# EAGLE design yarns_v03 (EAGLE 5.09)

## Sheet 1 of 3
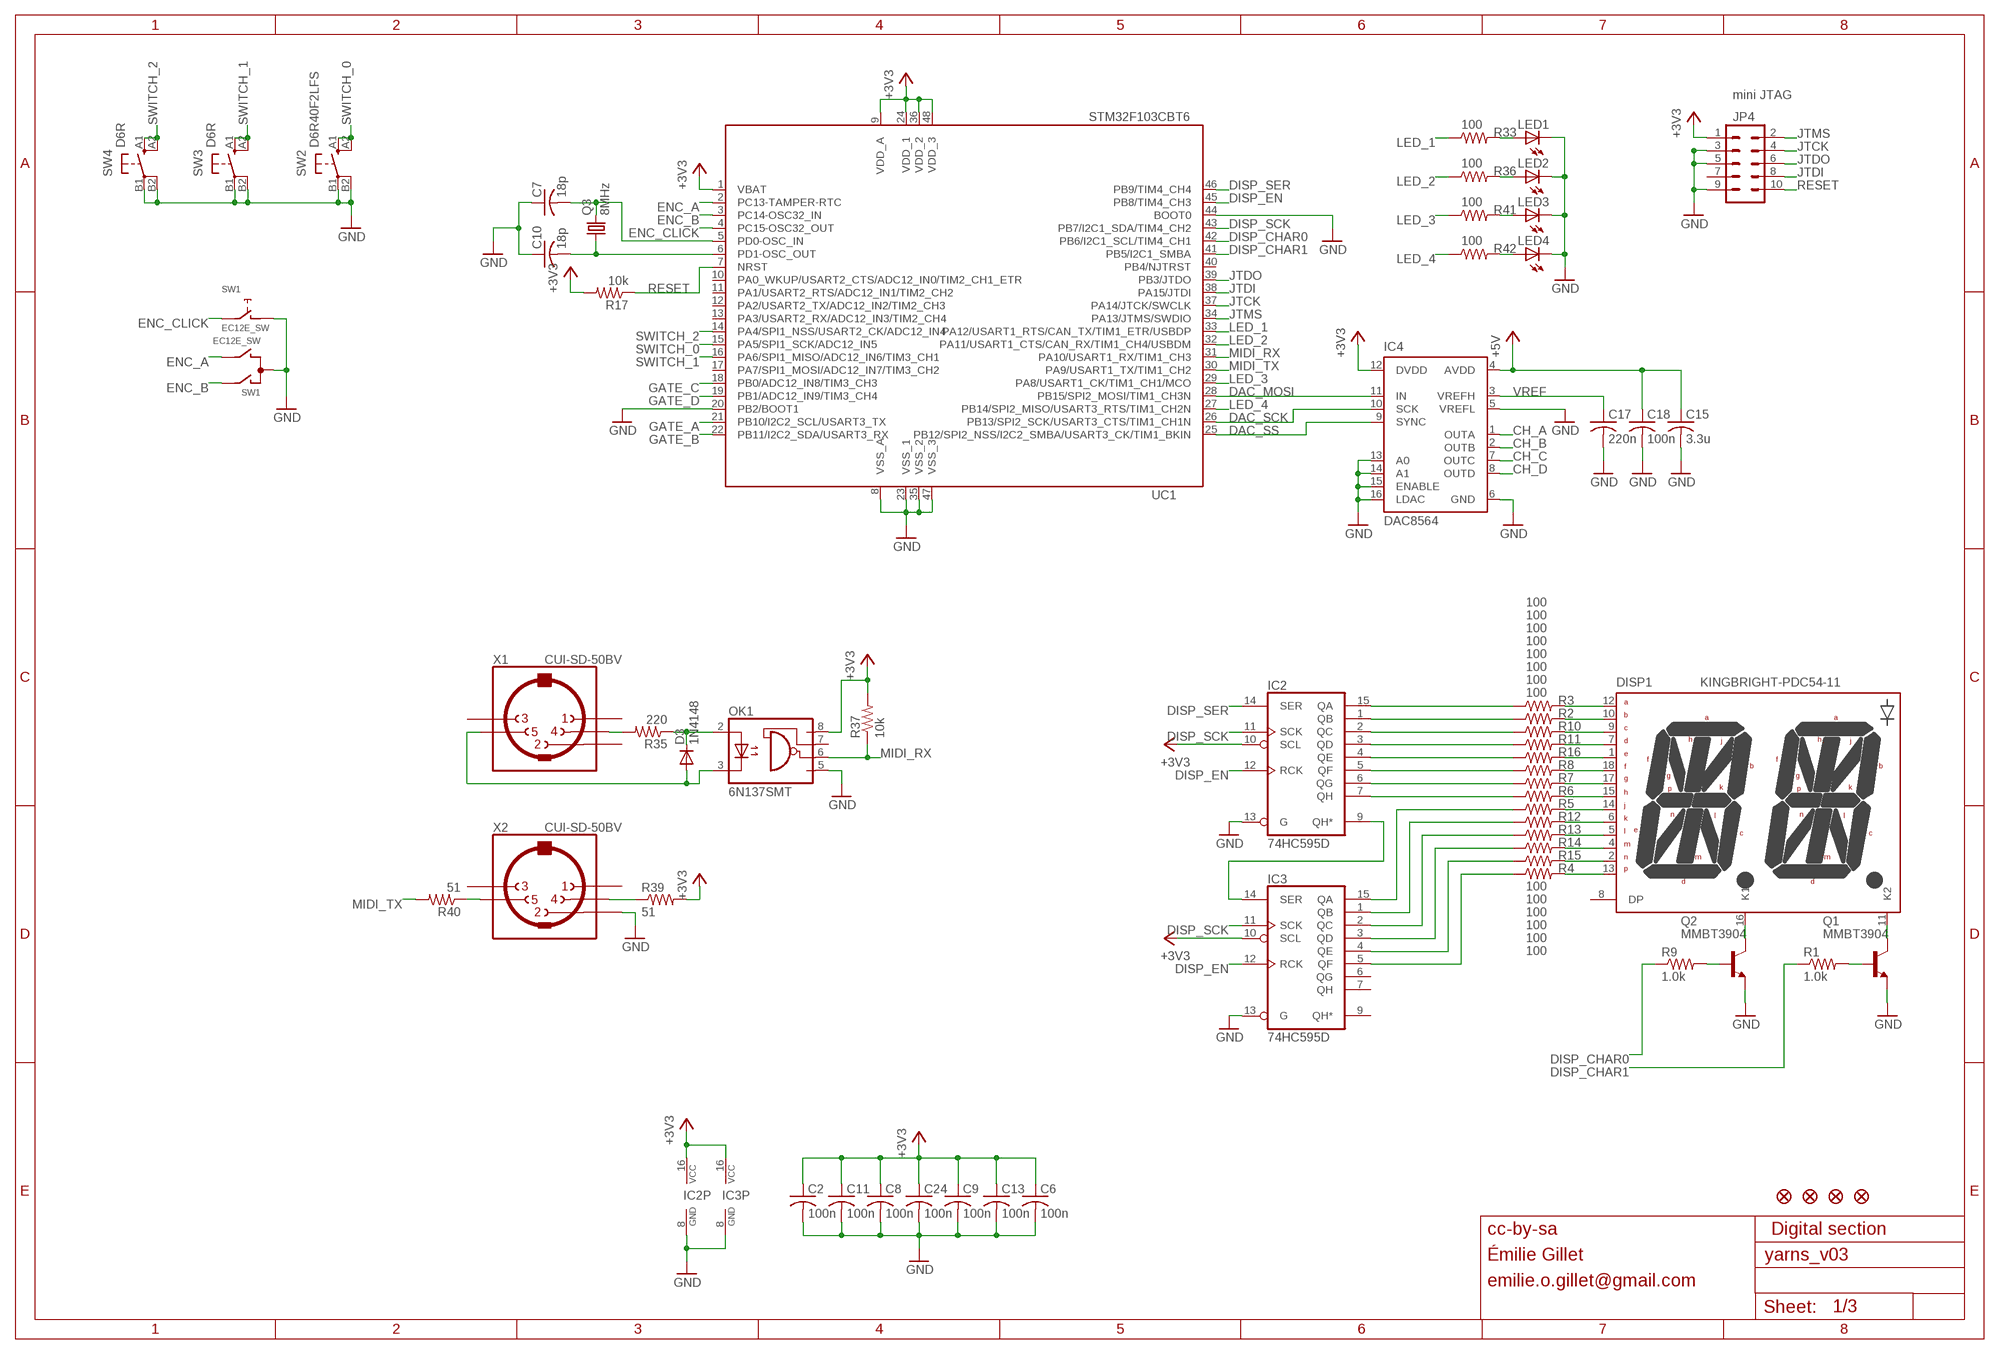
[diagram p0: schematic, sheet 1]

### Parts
C2  100n  C-USC0603  [C0603]
C6  100n  C-USC0603  [C0603]
C7  18p  C-USC0603  [C0603]
C8  100n  C-USC0603  [C0603]
C9  100n  C-USC0603  [C0603]
C10  18p  C-USC0603  [C0603]
C11  100n  C-USC0603  [C0603]
C13  100n  C-USC0603  [C0603]
C15  3.3u  C-USC0603  [C0603]
C17  220n  C-USC0603  [C0603]
C18  100n  C-USC0603  [C0603]
C24  100n  C-USC0603  [C0603]
D3  1N4148  DIODE-SOD323-W  [SOD323-W]
DISP1  KINGBRIGHT-PDC54-11  [PDC54]
F1  FIDUCIAL1X2  [FIDUCIAL-1X2]
F3  FIDUCIAL1X2  [FIDUCIAL-1X2]
F5  FIDUCIAL1X2  [FIDUCIAL-1X2]
F6  FIDUCIAL1X2  [FIDUCIAL-1X2]
IC2  74HC595D  [SO16]
IC3  74HC595D  [SO16]
IC4  DAC8564  [SOP65P640X110-16N]
JP4  M05X2MINIJTAG  [2X5-1.27]
LED1  LED3MM  [LED3MM]
LED2  LED3MM  [LED3MM]
LED3  LED3MM  [LED3MM]
LED4  LED3MM  [LED3MM]
OK1  6N137SMT  [DIL8-SMD]
Q1  MMBT3904  MMBT3904LT1-NPN-SOT23-BEC  [SOT23-BEC]
Q2  MMBT3904  MMBT3904LT1-NPN-SOT23-BEC  [SOT23-BEC]
Q3  8MHz  CRYSTALHC49UP  [HC49UP]
R1  1.0k  R-US_R0603  [R0603]
R2  100  R-US_R0603  [R0603]
R3  100  R-US_R0603  [R0603]
R4  100  R-US_R0603  [R0603]
R5  100  R-US_R0603  [R0603]
R6  100  R-US_R0603  [R0603]
R7  100  R-US_R0603  [R0603]
R8  100  R-US_R0603  [R0603]
R9  1.0k  R-US_R0603  [R0603]
R10  100  R-US_R0603  [R0603]
R11  100  R-US_R0603  [R0603]
R12  100  R-US_R0603  [R0603]
R13  100  R-US_R0603  [R0603]
R14  100  R-US_R0603  [R0603]
R15  100  R-US_R0603  [R0603]
R16  100  R-US_R0603  [R0603]
R17  10k  R-US_R0603  [R0603]
R33  100  R-US_R0603  [R0603]
R35  220  R-US_R0603  [R0603]
R36  100  R-US_R0603  [R0603]
R37  10k  R-US_R0603  [R0603]
R39  51  R-US_R0603  [R0603]
R40  51  R-US_R0603  [R0603]
R41  100  R-US_R0603  [R0603]
R42  100  R-US_R0603  [R0603]
SW1  EC12E_SW  [ALPS_EC12E_SW]
SW2  D6R40F2LFS  D6R  [D6R]
SW3  D6R  [D6R]
SW4  D6R  [D6R]
UC1  STM32F103CBT6  STM32F103CB  [LQFP48]
X1  CUI-SD-50BV  MAB5SHCUI-SD-50BV  [SD-50BV]
X2  CUI-SD-50BV  MAB5SHCUI-SD-50BV  [SD-50BV]

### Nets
+3V3: C2.1 C6.1 C8.1 C9.1 C11.1 C13.1 C24.1 IC2.10(SCL) IC2.16(VCC) IC3.10(SCL) IC3.16(VCC) IC4.12(DVDD) JP4.1 OK1.8(VCC) R17.2 R37.2 R39.2 UC1.1(VBAT) UC1.9(VDD_A) UC1.24(VDD_1) UC1.36(VDD_2) UC1.48(VDD_3) ; also sheet 3
+5V: C15.1 C18.1 IC4.4(AVDD) ; also sheet 3
CH_A: IC4.1(OUTA) ; also sheet 2
CH_B: IC4.2(OUTB) ; also sheet 2
CH_C: IC4.7(OUTC) ; also sheet 2
CH_D: IC4.8(OUTD) ; also sheet 2
DAC_MOSI: IC4.11(IN) UC1.28(PB15/SPI2_MOSI/TIM1_CH3N)
DAC_SCK: IC4.10(SCK) UC1.26(PB13/SPI2_SCK/USART3_CTS/TIM1_CH1N)
DAC_SS: IC4.9(SYNC) UC1.25(PB12/SPI2_NSS/I2C2_SMBA/USART3_CK/TIM1_BKIN)
DISP_CHAR0: R9.1 UC1.42(PB6/I2C1_SCL/TIM4_CH1)
DISP_CHAR1: R1.1 UC1.41(PB5/I2C1_SMBA)
DISP_EN: IC2.12(RCK) IC3.12(RCK) UC1.45(PB8/TIM4_CH3)
DISP_SCK: IC2.11(SCK) IC3.11(SCK) UC1.43(PB7/I2C1_SDA/TIM4_CH2)
DISP_SER: IC2.14(SER) UC1.46(PB9/TIM4_CH4)
ENC_A: SW1.B UC1.2(PC13-TAMPER-RTC)
ENC_B: SW1.A UC1.3(PC14-OSC32_IN)
ENC_CLICK: SW1.E UC1.4(PC15-OSC32_OUT)
GATE_A: UC1.21(PB10/I2C2_SCL/USART3_TX) ; also sheet 2
GATE_B: UC1.22(PB11/I2C2_SDA/USART3_RX) ; also sheet 2
GATE_C: UC1.18(PB0/ADC12_IN8/TIM3_CH3) ; also sheet 2
GATE_D: UC1.19(PB1/ADC12_IN9/TIM3_CH4) ; also sheet 2
GND: C2.2 C6.2 C7.1 C8.2 C9.2 C10.1 C11.2 C13.2 C15.2 C17.2 C18.2 C24.2 IC2.8(GND) IC2.13(G) IC3.8(GND) IC3.13(G) IC4.5(VREFL) IC4.6(GND) IC4.13(A0) IC4.14(A1) IC4.15(ENABLE) IC4.16(LDAC) JP4.3 JP4.5 JP4.9 LED1.K(C) LED2.K(C) LED3.K(C) LED4.K(C) OK1.5(GND) Q1.E Q2.E SW1.C SW1.D SW2.B1(P) SW2.B2(P1) SW3.B1(P) SW3.B2(P1) SW4.B1(P) SW4.B2(P1) UC1.8(VSS_A) UC1.20(PB2/BOOT1) UC1.23(VSS_1) UC1.35(VSS_2) UC1.44(BOOT0) UC1.47(VSS_3) X2.2 ; also sheet 2,3
JTCK: JP4.4 UC1.37(PA14/JTCK/SWCLK)
JTDI: JP4.8 UC1.38(PA15/JTDI)
JTDO: JP4.6 UC1.39(PB3/JTDO)
JTMS: JP4.2 UC1.34(PA13/JTMS/SWDIO)
LED_1: R33.1 UC1.33(PA12/USART1_RTS/CAN_TX/TIM1_ETR/USBDP)
LED_2: R36.1 UC1.32(PA11/USART1_CTS/CAN_RX/TIM1_CH4/USBDM)
LED_3: R41.1 UC1.29(PA8/USART1_CK/TIM1_CH1/MCO)
LED_4: R42.1 UC1.27(PB14/SPI2_MISO/USART3_RTS/TIM1_CH2N)
MIDI_RX: OK1.6(VO) R37.1 UC1.31(PA10/USART1_RX/TIM1_CH3)
MIDI_TX: R40.2 UC1.30(PA9/USART1_TX/TIM1_CH2)
N$1: DISP1.16(K1) Q2.C
N$3: DISP1.11(K2) Q1.C
N$4: C7.2 Q3.2 UC1.5(PD0-OSC_IN)
N$5: C10.2 Q3.1 UC1.6(PD1-OSC_OUT)
N$6: Q2.B R9.2
N$7: Q1.B R1.2
N$8: D3.C OK1.2(A) R35.1
N$9: R35.2 X1.4
N$10: R40.1 X2.5
N$11: DISP1.17(G) R7.2
N$12: D3.A OK1.3(C) X1.5
N$13: R39.1 X2.4
N$15: DISP1.12(A) R3.2
N$16: DISP1.10(B) R2.2
N$17: DISP1.9(C) R10.2
N$18: DISP1.7(D) R11.2
N$19: DISP1.1(E) R16.2
N$20: DISP1.18(F) R8.2
N$22: DISP1.15(H) R6.2
N$23: DISP1.14(J) R5.2
N$24: DISP1.6(K) R12.2
N$25: DISP1.5(L) R13.2
N$26: DISP1.4(M) R14.2
N$27: DISP1.2(N) R15.2
N$28: DISP1.13(P) R4.2
N$30: IC2.7(QH) R6.1
N$31: IC2.9(QH*) IC3.14(SER)
N$32: IC2.15(QA) R3.1
N$33: IC2.1(QB) R2.1
N$34: IC2.2(QC) R10.1
N$35: IC2.3(QD) R11.1
N$36: IC2.4(QE) R16.1
N$37: IC2.5(QF) R8.1
N$38: IC2.6(QG) R7.1
N$39: IC3.15(QA) R5.1
N$40: IC3.1(QB) R12.1
N$41: IC3.2(QC) R13.1
N$42: IC3.3(QD) R14.1
N$43: IC3.4(QE) R15.1
N$44: IC3.5(QF) R4.1
N$54: LED1.A R33.2
N$65: LED2.A R36.2
N$66: LED3.A R41.2
N$67: LED4.A R42.2
RESET: JP4.10 R17.1 UC1.7(NRST)
SWITCH_0: SW2.A1(S) SW2.A2(S1) UC1.15(PA5/SPI1_SCK/ADC12_IN5)
SWITCH_1: SW3.A1(S) SW3.A2(S1) UC1.16(PA6/SPI1_MISO/ADC12_IN6/TIM3_CH1)
SWITCH_2: SW4.A1(S) SW4.A2(S1) UC1.14(PA4/SPI1_NSS/USART2_CK/ADC12_IN4)
VREF: C17.1 IC4.3(VREFH) ; also sheet 2
Unconnected: DISP1.8(DP) IC3.6(QG) IC3.7(QH) IC3.9(QH*) JP4.7 OK1.7(VE) SW1.GND1(G) SW1.GND2(G) UC1.10(PA0_WKUP/USART2_CTS/ADC12_IN0/TIM2_CH1_ETR) UC1.11(PA1/USART2_RTS/ADC12_IN1/TIM2_CH2) UC1.12(PA2/USART2_TX/ADC12_IN2/TIM2_CH3) UC1.13(PA3/USART2_RX/ADC12_IN3/TIM2_CH4) UC1.17(PA7/SPI1_MOSI/ADC12_IN7/TIM3_CH2) UC1.40(PB4/NJTRST) X1.1 X1.2 X1.3 X2.1 X2.3

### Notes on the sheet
- mini JTAG
- cc-by-sa | Digital section
- Émilie Gillet
- emilie.o.gillet@gmail.com

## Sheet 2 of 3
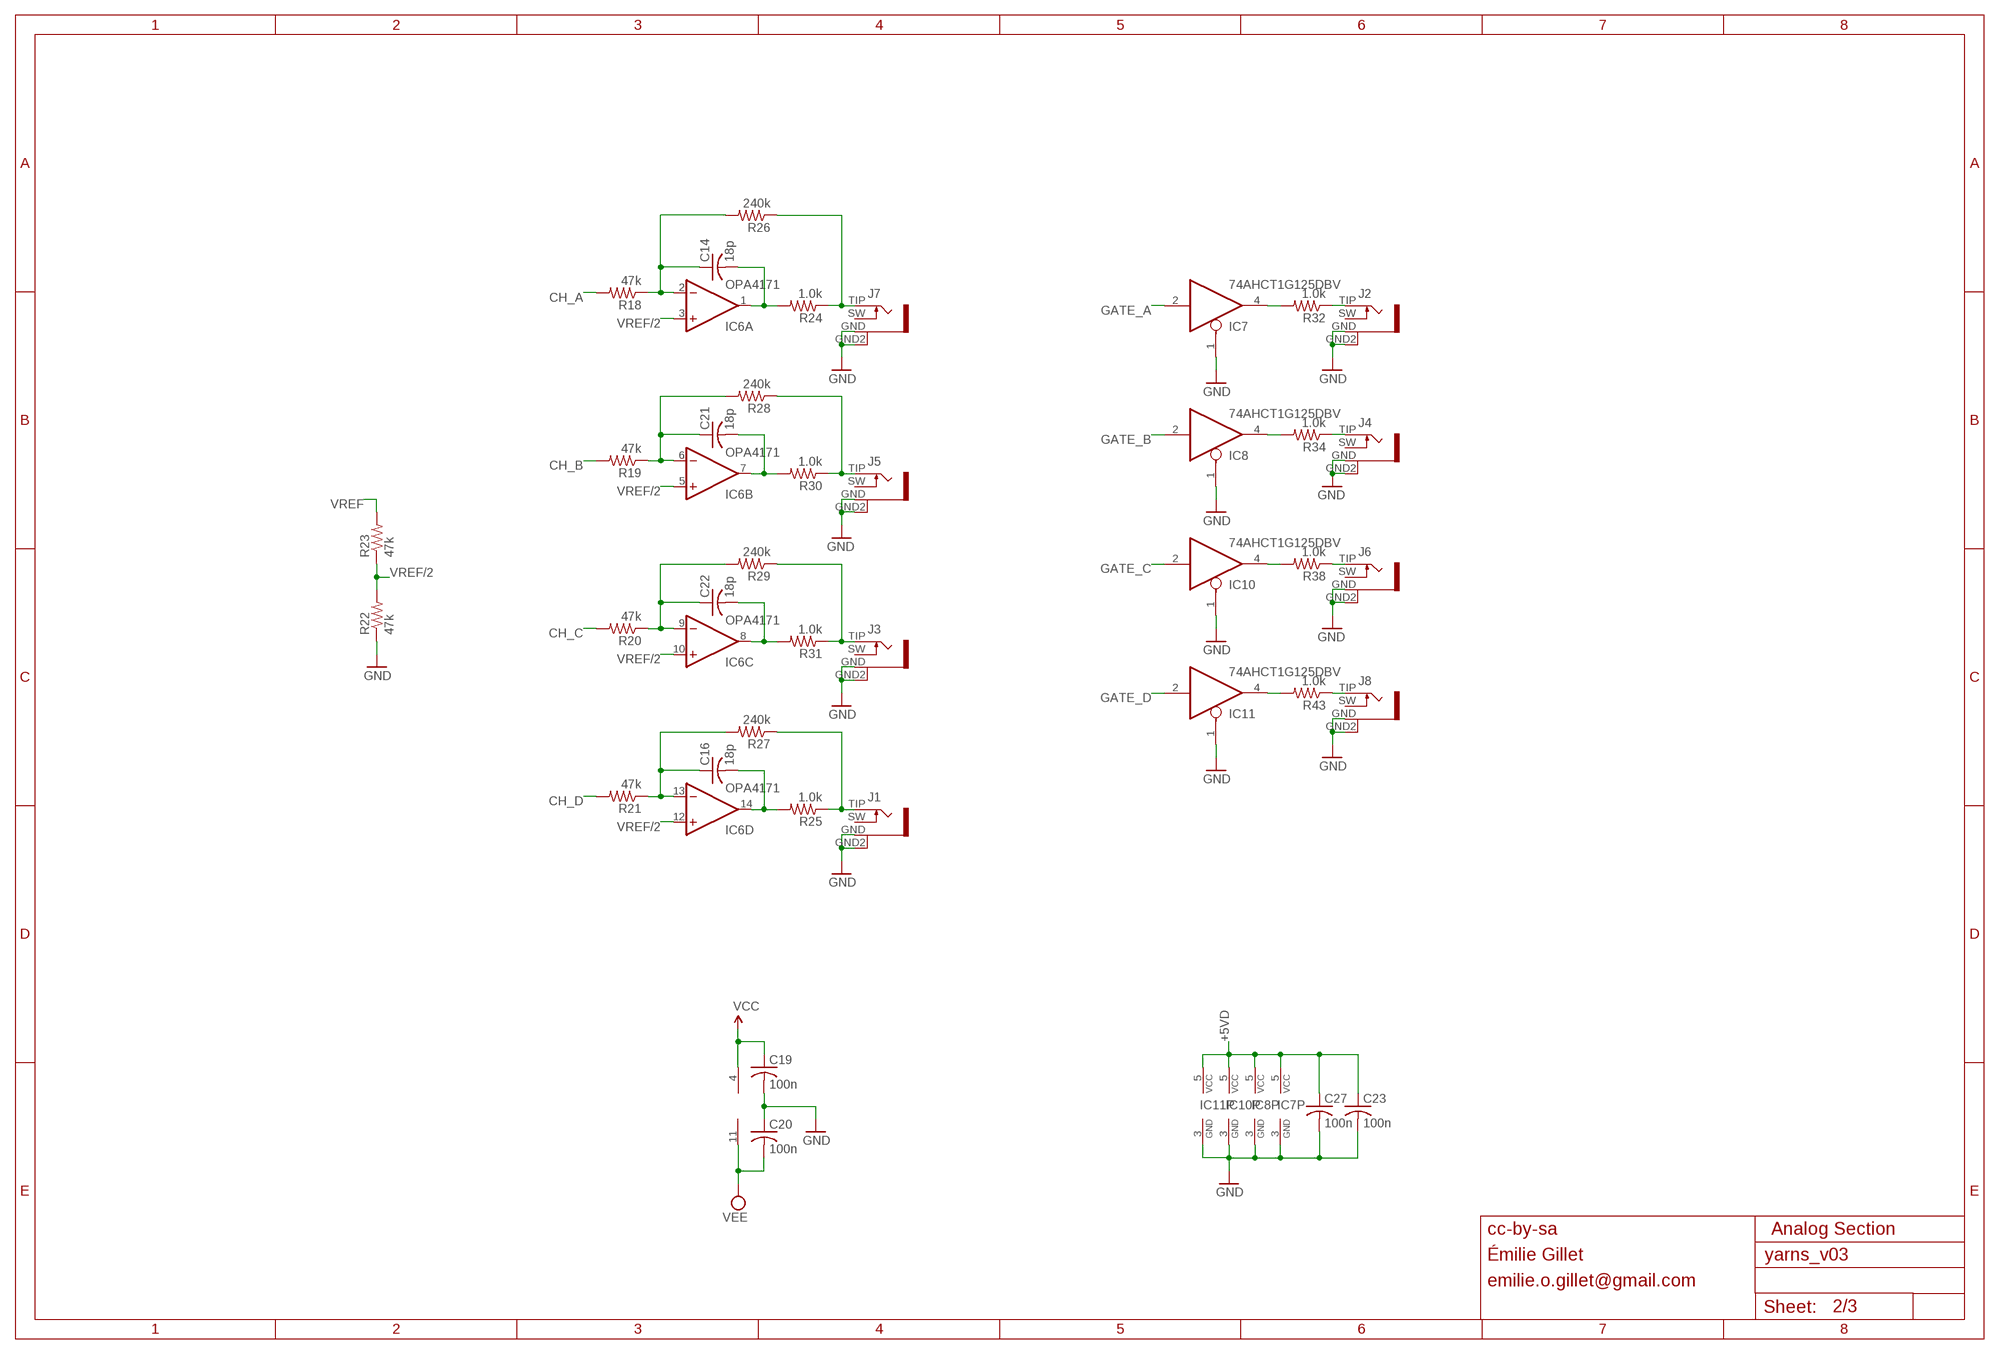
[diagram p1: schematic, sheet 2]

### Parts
C14  18p  C-USC0603  [C0603]
C16  18p  C-USC0603  [C0603]
C19  100n  C-USC0603  [C0603]
C20  100n  C-USC0603  [C0603]
C21  18p  C-USC0603  [C0603]
C22  18p  C-USC0603  [C0603]
C23  100n  C-USC0603  [C0603]
C27  100n  C-USC0603  [C0603]
IC6  OPA4171  TL074D  [SO14]
IC7  74AHCT1G125DBV  [SOT23-5]
IC8  74AHCT1G125DBV  [SOT23-5]
IC10  74AHCT1G125DBV  [SOT23-5]
IC11  74AHCT1G125DBV  [SOT23-5]
J1  PJ301WQP  [WQP_PJ_301BM]
J2  PJ301WQP  [WQP_PJ_301BM]
J3  PJ301WQP  [WQP_PJ_301BM]
J4  PJ301WQP  [WQP_PJ_301BM]
J5  PJ301WQP  [WQP_PJ_301BM]
J6  PJ301WQP  [WQP_PJ_301BM]
J7  PJ301WQP  [WQP_PJ_301BM]
J8  PJ301WQP  [WQP_PJ_301BM]
R18  47k  R-US_R0603  [R0603]
R19  47k  R-US_R0603  [R0603]
R20  47k  R-US_R0603  [R0603]
R21  47k  R-US_R0603  [R0603]
R22  47k  R-US_R0603  [R0603]
R23  47k  R-US_R0603  [R0603]
R24  1.0k  R-US_R0603  [R0603]
R25  1.0k  R-US_R0603  [R0603]
R26  240k  R-US_R0603  [R0603]
R27  240k  R-US_R0603  [R0603]
R28  240k  R-US_R0603  [R0603]
R29  240k  R-US_R0603  [R0603]
R30  1.0k  R-US_R0603  [R0603]
R31  1.0k  R-US_R0603  [R0603]
R32  1.0k  R-US_R0603  [R0603]
R34  1.0k  R-US_R0603  [R0603]
R38  1.0k  R-US_R0603  [R0603]
R43  1.0k  R-US_R0603  [R0603]

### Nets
+5VD: C23.1 C27.1 IC7.5(VCC) IC8.5(VCC) IC10.5(VCC) IC11.5(VCC) ; also sheet 3
AOUT: J2.TIP R32.1
CH_A: R18.2 ; also sheet 1
CH_B: R19.2 ; also sheet 1
CH_C: R20.2 ; also sheet 1
CH_D: R21.2 ; also sheet 1
GATE_A: IC7.2(I) ; also sheet 1
GATE_B: IC8.2(I) ; also sheet 1
GATE_C: IC10.2(I) ; also sheet 1
GATE_D: IC11.2(I) ; also sheet 1
GND: C19.2 C20.1 C23.2 C27.2 IC7.1(OE) IC7.3(GND) IC8.1(OE) IC8.3(GND) IC10.1(OE) IC10.3(GND) IC11.1(OE) IC11.3(GND) J1.GND J1.GND2 J2.GND J2.GND2 J3.GND J3.GND2 J4.GND J4.GND2 J5.GND J5.GND2 J6.GND J6.GND2 J7.GND J7.GND2 J8.GND J8.GND2 R22.1 ; also sheet 1,3
N$2: C22.1 IC6.9(C:-IN) R20.1 R29.2
N$14: IC7.4(O) R32.2
N$29: IC8.4(O) R34.2
N$45: IC10.4(O) R38.2
N$46: IC11.4(O) R43.2
N$47: C14.2 IC6.1(A:OUT) R24.2
N$48: J6.TIP R38.1
N$49: J8.TIP R43.1
N$50: C21.2 IC6.7(B:OUT) R30.2
N$51: C22.2 IC6.8(C:OUT) R31.2
N$52: C16.2 IC6.14(D:OUT) R25.2
N$53: J7.TIP R24.1 R26.1
N$55: J3.TIP R29.1 R31.1
N$57: J4.TIP R34.1
N$58: J1.TIP R25.1 R27.1
N$59: C16.1 IC6.13(D:-IN) R21.1 R27.2
N$60: C21.1 IC6.6(B:-IN) R19.1 R28.2
N$61: C14.1 IC6.2(A:-IN) R18.1 R26.2
N$63: J5.TIP R28.1 R30.1
VCC: C19.1 IC6.4(P:V+) ; also sheet 3
VEE: C20.2 IC6.11(P:V-) ; also sheet 3
VREF: R23.2 ; also sheet 1
VREF/2: IC6.3(A:+IN) IC6.5(B:+IN) IC6.10(C:+IN) IC6.12(D:+IN) R22.2 R23.1
Unconnected: J1.SW J2.SW J3.SW J4.SW J5.SW J6.SW J7.SW J8.SW

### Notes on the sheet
- cc-by-sa | Analog Section
- Émilie Gillet
- emilie.o.gillet@gmail.com

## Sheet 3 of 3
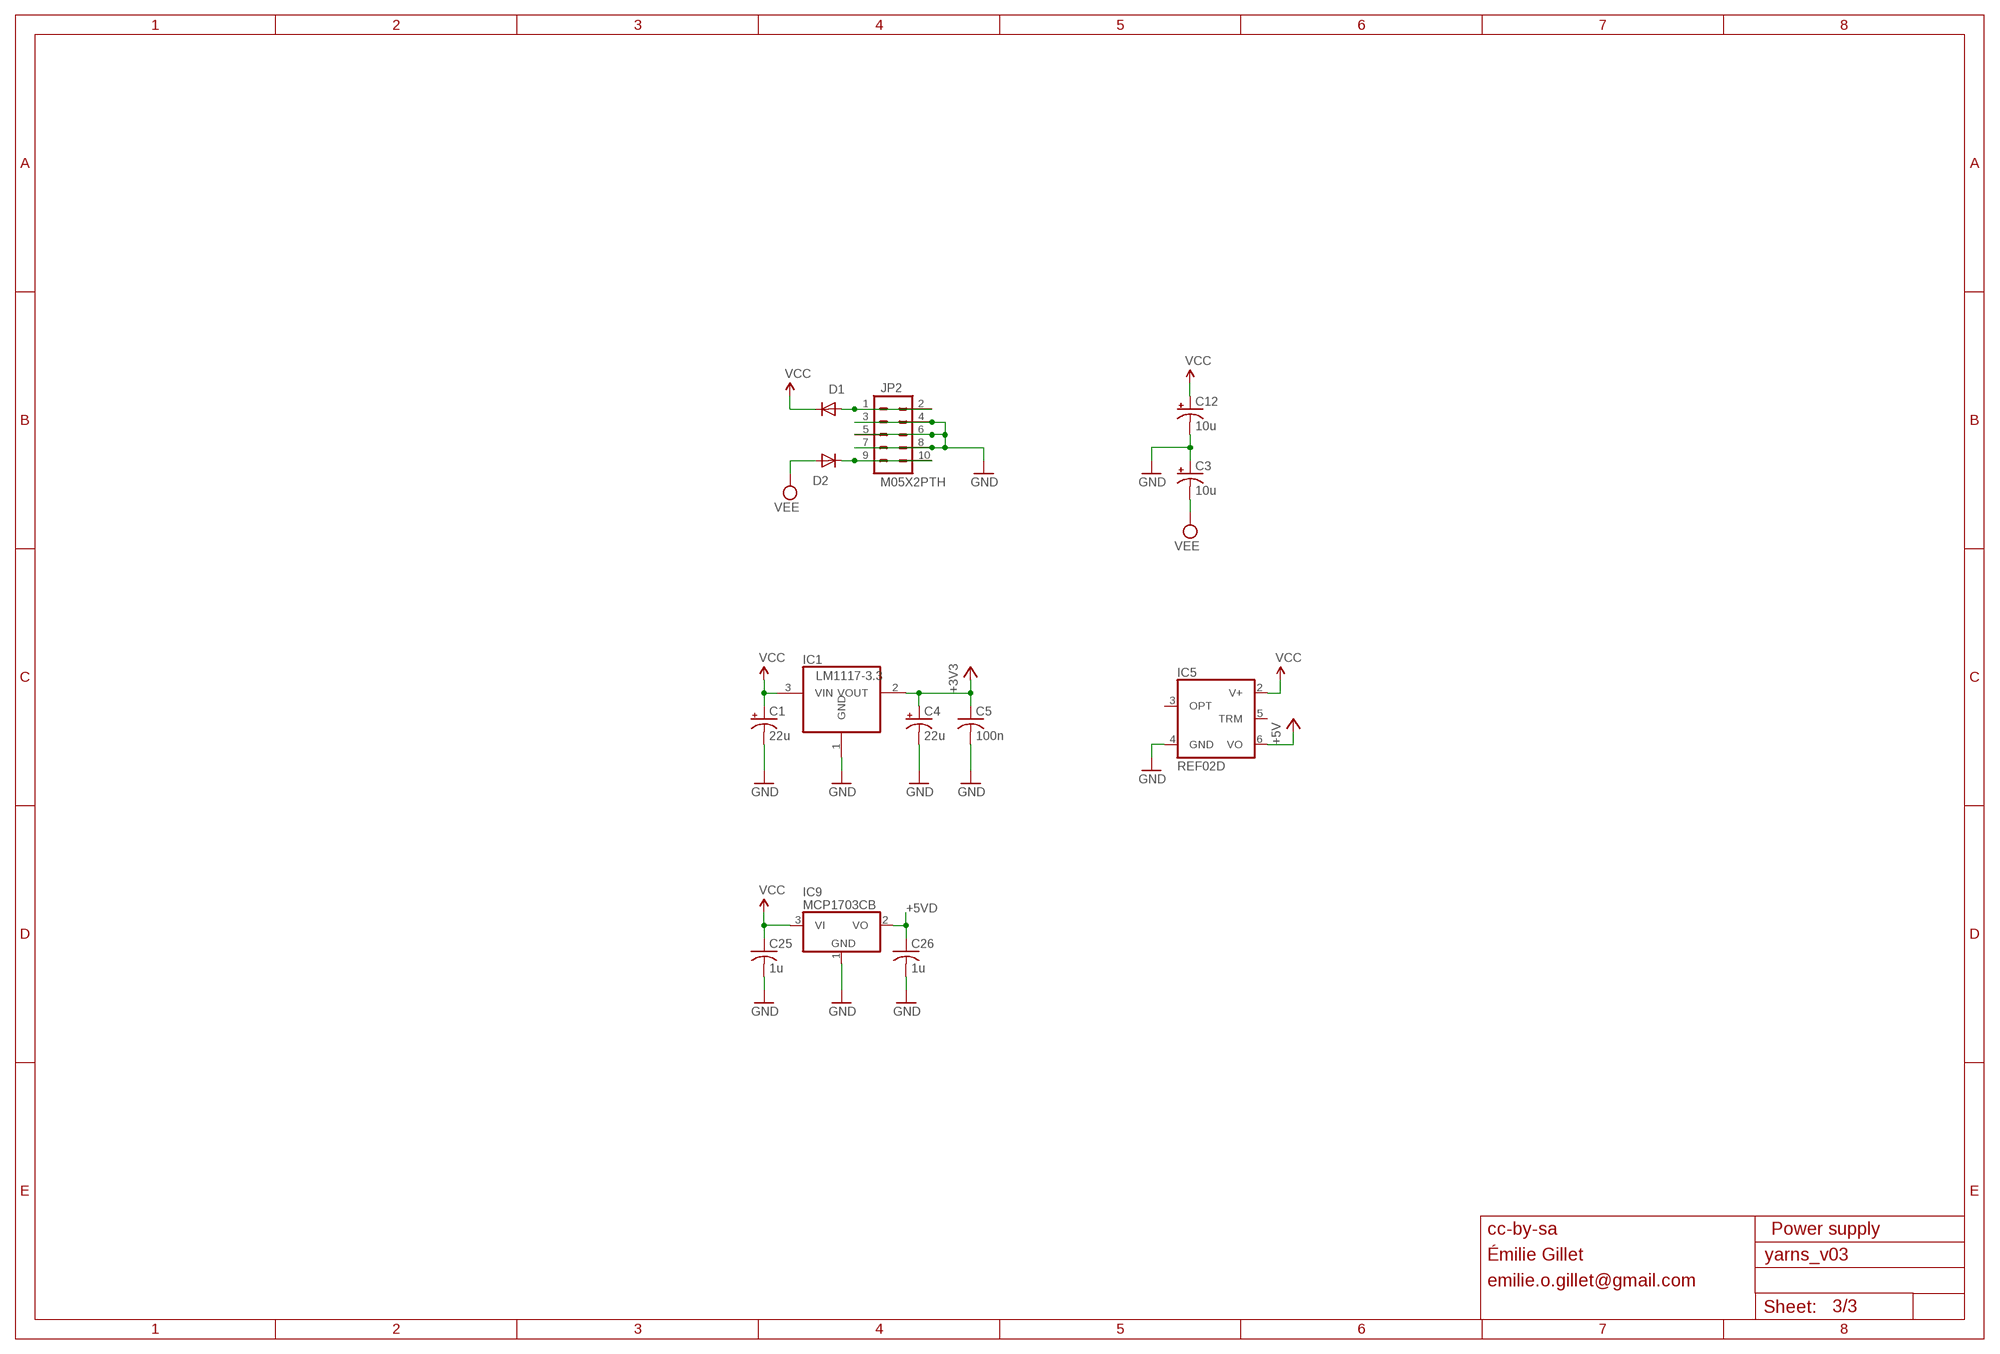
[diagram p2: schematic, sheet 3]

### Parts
C1  22u  CPOL-USC  [PANASONIC_C]
C3  10u  CPOL-USA  [PANASONIC_A]
C4  22u  CPOL-USC  [PANASONIC_C]
C5  100n  C-USC0603  [C0603]
C12  10u  CPOL-USA  [PANASONIC_A]
C25  1u  C-USC0603  [C0603]
C26  1u  C-USC0603  [C0603]
D1  1N5819HW  DIODE-SOD123  [SOD123]
D2  1N5819HW  DIODE-SOD123  [SOD123]
IC1  LM1117-3.3  REG1117  [SOT223]
IC5  REF02D  [SO08]
IC9  MCP1703CB  [SOT23]
JP2  M05X2PTH  [AVR_ICSP]

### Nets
+3V3: C4.+ C5.1 IC1.2(VOUT) ; also sheet 1
+5V: IC5.6(VO) ; also sheet 1
+5VD: C26.1 IC9.2(VO) ; also sheet 2
GND: C1.- C3.+ C4.- C5.2 C12.- C25.2 C26.2 IC1.1(GND) IC5.4(GND) IC9.1(GND) JP2.3 JP2.4 JP2.5 JP2.6 JP2.7 JP2.8 ; also sheet 1,2
N$56: D1.A JP2.1 JP2.2
N$64: D2.C JP2.9 JP2.10
VCC: C1.+ C12.+ C25.1 D1.C IC1.3(VIN) IC5.2(V+) IC9.3(VI) ; also sheet 2
VEE: C3.- D2.A ; also sheet 2
Unconnected: IC5.3(OPT) IC5.5(TRM)

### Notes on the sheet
- cc-by-sa | Power supply
- Émilie Gillet
- emilie.o.gillet@gmail.com

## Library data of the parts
C1 C3 C4 C12 = rcl:CPOL-US: POLARIZED CAPACITOR, American symbol
C2 C5-C11 C13-C27 = rcl:C-US: CAPACITOR, American symbol
D1-D3 = diode:DIODE-: DIODE
DISP1 = og-display:KINGBRIGHT-PDC54-11: Kingbright PDC54-11GWA ; also compatible with LITE-On LTP-3784G or Avago HDSP-A27C
F1 F3 F5 F6 = SparkFun:FIDUCIAL: Fiducial Alignment Points
IC1 = og-vreg:REG1117: 800mA and 1A Low Dropout (LDO) Positive Regulator 1.8V, 2.5V, 2.85V, 3.3V, 5V, and Adj
IC2 IC3 = 74xx-eu:74*595: 8-bit SHIFT REGISTER, output latch
IC4 = og-dac:DAC8564
IC5 = linear:REF02: VOLTAGE REFERENCE
IC6 = gm-ics:TL074: OP AMP
IC7 IC8 IC10 IC11 = 74xx-little-us:74*1G125: Single Bus Buffer Gate with 3-State Output
IC9 = linear:MCP1703: 250 mA, 16V, Low Quiescent Current LDO Regulator Source: http://ww1.microchip.com/downloads/en/DeviceDoc/22049b.pdf
J1-J8 = og-pj301:PJ301
JP2 JP4 = og-header:M05X2: Header 5x2 Standard 10-pin dual row 0.1" header. Commonly used with AVR-ISP. Use with Spark Fun Electronics SKU: PRT-00778
LED1-LED4 = led:LED: LED
OK1 = og-optocouplers:6N137: MOTOROLA OPTO COUPLER
Q1 Q2 = transistor:*-NPN-: NPN Transistror BF959 corrected 2008.03.06
Q3 = crystal:CRYSTAL: CRYSTAL
R1-R43 = rcl:R-US_: RESISTOR, American symbol
SW1 = og-encoder:EC12E_SW: ALPS rotary Encoder EC12E series with switch
SW2-SW4 = og-switch:D6R: C&K D6R
UC1 = stm32:STM32F103CB
X1 X2 = og-midi:MAB5SH: Female CONNECTOR 5 pins 90 deg. with shield, horizontal (DIN 41524)

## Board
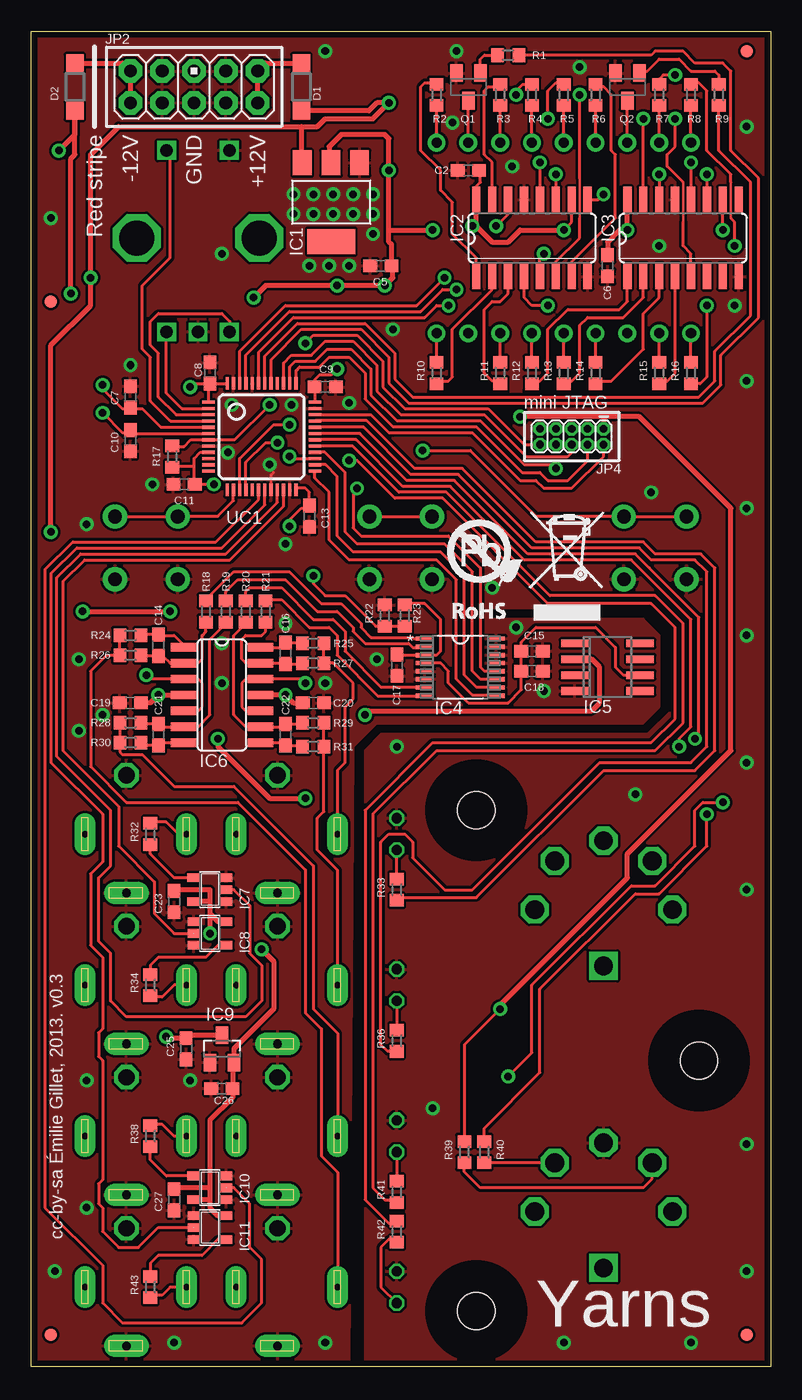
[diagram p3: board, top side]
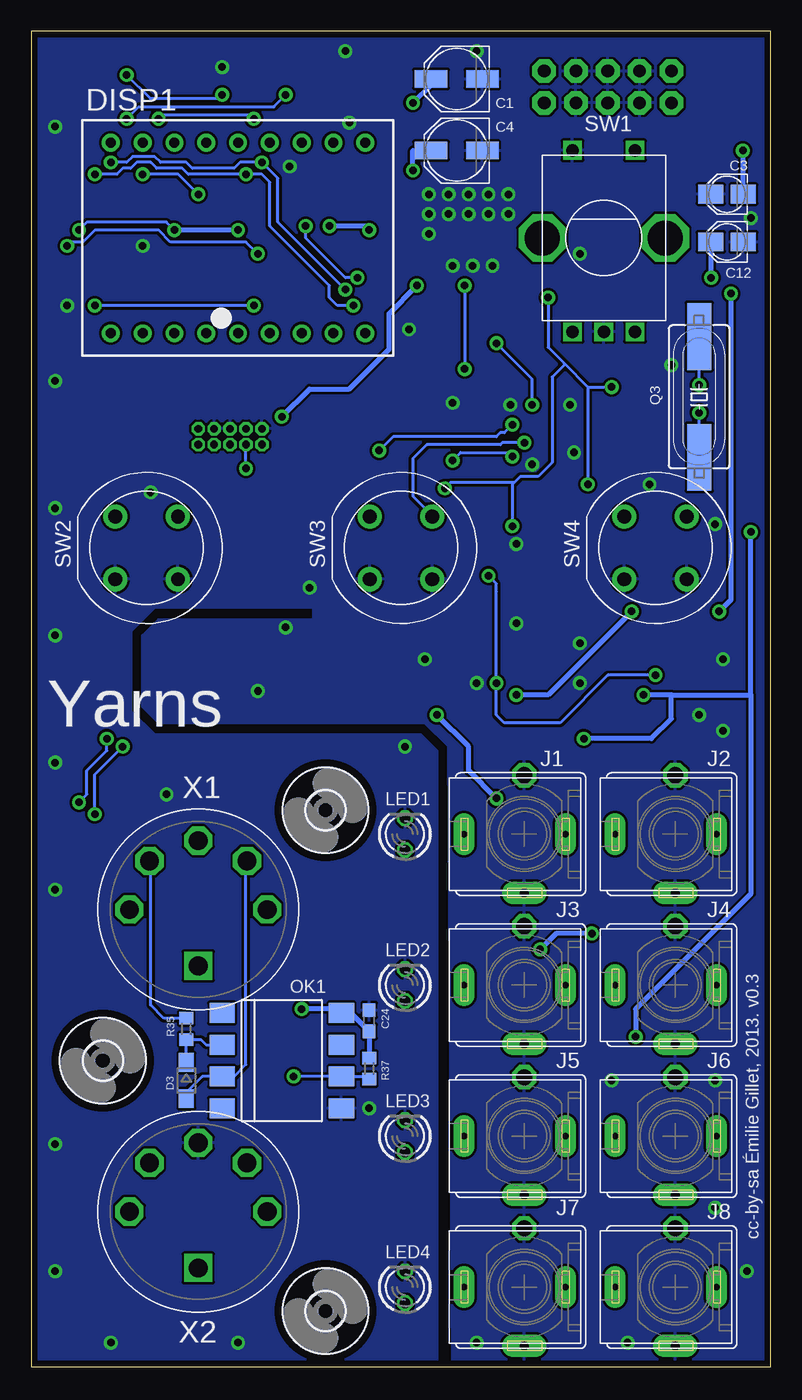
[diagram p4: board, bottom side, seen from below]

Size 59.03 x 106.68 mm. Coordinates in mm from the lower left corner, seen from the top.
Outline: 0,0 0,106.68 59.03,106.68 59.03,0 0,0
Copper layers (1*16): Top 0.035mm / dielectric 1.5mm / Bottom 0.035mm
Design rules "PCBCart-Standard": minimum track width 8mil, minimum drill 0.4mm, track to track 8mil, track to pad 8mil, pad to pad 8mil, via to via 8mil, smd to smd 8mil, copper to edge 20mil, drill to drill 8mil, minimum pad ring 8mil, minimum via ring 10mil, stop-mask expansion 3mil, vias tented up to drill 25mil, thermal gap 8mil

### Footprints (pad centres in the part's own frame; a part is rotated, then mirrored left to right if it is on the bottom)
PANASONIC_C = smd 2.6 x 1.4: + 2.05,0; - -2.05,0
C0603 = smd 1.1 x 1: 1 -0.85,0; 2 0.85,0
PANASONIC_A = smd 2 x 1.5: + 1.3,0; - -1.3,0
SOD123 = smd 1.4 x 1.4: A 1.9,0; C -1.9,0
SOD323-W = smd 1.5 x 1.2: A 1.45,0; C -1.45,0
PDC54 = drill 0.8 pad 1.422 round: 1 -10.16,-7.62; 2 -7.62,-7.62; 3 -5.08,-7.62; 4 -2.54,-7.62; 5 0,-7.62; 6 2.54,-7.62; 7 5.08,-7.62; 8 7.62,-7.62; 9 10.16,-7.62; 10 10.16,7.62; 11 7.62,7.62; 12 5.08,7.62; 13 2.54,7.62; 14 0,7.62; 15 -2.54,7.62; 16 -5.08,7.62; 17 -7.62,7.62; 18 -10.16,7.62
FIDUCIAL-1X2 = smd 1 x 1: 1 0,0
SOT223 = smd 1.499 x 2.007: 1 -2.261,-3.15; 2 0.025,-3.15; 3 2.311,-3.15 | smd 3.81 x 2.007: 4 0,3.15
SO16 = smd 0.66 x 2.032: 1 -4.445,-3.073; 2 -3.175,-3.073; 3 -1.905,-3.073; 4 -0.635,-3.073; 5 0.635,-3.073; 6 1.905,-3.073; 7 3.175,-3.073; 8 4.445,-3.073; 9 4.445,3.073; 10 3.175,3.073; 11 1.905,3.073; 12 0.635,3.073; 13 -0.635,3.073; 14 -1.905,3.073; 15 -3.175,3.073; 16 -4.445,3.073
SOP65P640X110-16N = smd 1.422 x 0.356: 1 -2.845,2.286; 2 -2.845,1.626; 3 -2.845,0.965; 4 -2.845,0.33; 5 -2.845,-0.33; 6 -2.845,-0.965; 7 -2.845,-1.626; 8 -2.845,-2.286; 9 2.845,-2.286; 10 2.845,-1.626; 11 2.845,-0.965; 12 2.845,-0.33; 13 2.845,0.33; 14 2.845,0.965; 15 2.845,1.626; 16 2.845,2.286
SO08 = smd 0.6 x 2.2: 1 -1.905,-2.6; 2 -0.635,-2.6; 3 0.635,-2.6; 4 1.905,-2.6; 5 1.905,2.6; 6 0.635,2.6; 7 -0.635,2.6; 8 -1.905,2.6
SO14 = smd 0.66 x 2.032: 1 -3.81,-3.073; 2 -2.54,-3.073; 3 -1.27,-3.073; 4 0,-3.073; 5 1.27,-3.073; 6 2.54,-3.073; 7 3.81,-3.073; 8 3.81,3.073; 9 2.54,3.073; 10 1.27,3.073; 11 0,3.073; 12 -1.27,3.073; 13 -2.54,3.073; 14 -3.81,3.073
SOT23-5 = smd 0.69 x 0.99: 1 -0.95,-1.29; 2 0,-1.29; 3 0.95,-1.29; 4 0.95,1.3; 5 -0.95,1.3
SOT23 = smd 1 x 1.4: 1 -0.95,-1.1; 2 0.95,-1.1; 3 0,1.1
WQP_PJ_301BM = drill 0.7 pad 1.778 long: GND -4.7,0 | drill 1.3 octagon: GND2 4.7,0 | drill 0.508 pad 1.676 long: SW 0,-3.3; TIP 0,4.8
AVR_ICSP = drill 1.016 pad 1.88 octagon: 1 -1.27,5.08; 2 1.27,5.08; 3 -1.27,2.54; 4 1.27,2.54; 5 -1.27,0; 6 1.27,0; 7 -1.27,-2.54; 8 1.27,-2.54; 9 -1.27,-5.08; 10 1.27,-5.08
2X5-1.27 = drill 0.61 pad 1.067 octagon: 1 -1.27,3.81; 2 0,3.81; 3 -1.27,2.54; 4 0,2.54; 5 -1.27,1.27; 6 0,1.27; 7 -1.27,0; 8 0,0; 9 -1.27,-1.27; 10 0,-1.27
LED3MM = drill 0.813 octagon: A -1.27,0; K 1.27,0
DIL8-SMD = smd 1.6 x 2: 1 -3.81,-4.77; 2 -1.27,-4.77; 3 1.27,-4.77; 4 3.81,-4.77; 5 3.81,4.77; 6 1.27,4.77; 7 -1.27,4.77; 8 -3.81,4.77
SOT23-BEC = smd 1 x 1.4: B -0.95,-1.1; C 0,1.1; E 0.95,-1.1
HC49UP = smd 5.334 x 1.93: 1 -4.826,0; 2 4.826,0
R0603 = smd 1 x 1.1: 1 -0.85,0; 2 0.85,0
ALPS_EC12E_SW = drill 1 square: A -2.5,-7.5; B 2.5,-7.5; C 0,-7.5; D -2.5,7; E 2.5,7 | drill 2.8 octagon: GND1 -4.9,0; GND2 4.9,0
D6R = drill 1.1 pad 1.93 round: A1 -2.5,2.5; A2 2.5,2.5; B1 -2.5,-2.5; B2 2.5,-2.5
3,0 = hole 3: 0,0
LQFP48 = smd 0.254 x 1: 1 -2.75,-4.25; 2 -2.25,-4.25; 3 -1.75,-4.25; 4 -1.25,-4.25; 5 -0.75,-4.25; 6 -0.25,-4.25; 7 0.25,-4.25; 8 0.75,-4.25; 9 1.25,-4.25; 10 1.75,-4.25; 11 2.25,-4.25; 12 2.75,-4.25; 25 2.75,4.25; 26 2.25,4.25; 27 1.75,4.25; 28 1.25,4.25; 29 0.75,4.25; 30 0.25,4.25; 31 -0.25,4.25; 32 -0.75,4.25; 33 -1.25,4.25; 34 -1.75,4.25; 35 -2.25,4.25; 36 -2.75,4.25 | smd 1 x 0.254: 13 4.25,-2.75; 14 4.25,-2.25; 15 4.25,-1.75; 16 4.25,-1.25; 17 4.25,-0.75; 18 4.25,-0.25; 19 4.25,0.25; 20 4.25,0.75; 21 4.25,1.25; 22 4.25,1.75; 23 4.25,2.25; 24 4.25,2.75; 37 -4.25,2.75; 38 -4.25,2.25; 39 -4.25,1.75; 40 -4.25,1.25; 41 -4.25,0.75; 42 -4.25,0.25; 43 -4.25,-0.25; 44 -4.25,-0.75; 45 -4.25,-1.25; 46 -4.25,-1.75; 47 -4.25,-2.25; 48 -4.25,-2.75
SD-50BV = drill 1.5 octagon: 1 -5.5,0; 2 0,5.5; 3 5.5,0; 4 -3.89,3.89; 5 3.89,3.89 | drill 1.5 square: P$3 0,-4.5

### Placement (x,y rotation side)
C1  25.06,102.87 180 bottom
C2  34.91,95.57 180 top
C3  3.47,93.66 180 bottom
C4  25.06,97.16 180 bottom
C5  27.92,87.95 180 top
C6  46.02,87.95 270 top
C7  7.92,77.47 270 top
C8  14.27,79.38 90 top
C9  23.47,78.26 0 top
C10  7.92,73.98 90 top
C11  12.2,70.49 180 top
C12  3.47,89.85 180 bottom
C13  22.2,67.94 270 top
C14  10.14,57.63 90 top
C15  39.98,57.15 0 top
C16  20.3,56.99 90 top
C17  29.19,56.04 270 top
C18  39.98,55.56 0 top
C19  7.92,53.02 180 top
C20  22.52,53.02 180 top
C21  10.14,50.48 270 top
C22  20.3,50.48 270 top
C23  11.41,37.15 270 top
C24  32.05,27.62 90 bottom
C25  12.36,25.4 270 top
C26  15.22,22.23 180 top
C27  11.41,13.34 270 top
D1  21.57,102.23 90 top
D2  3.47,102.23 270 top
D3  46.65,22.86 270 bottom
DISP1  42.52,90.17 0 bottom
F1  57.13,105.09 0 top
F3  1.57,85.09 0 top
F5  1.57,2.54 0 top
F6  57.13,2.54 0 top
IC1  23.95,93.03 180 top
IC2  39.98,90.17 0 top
IC3  52.05,90.17 0 top
IC4  34.27,55.88 0 top
IC5  46.02,55.88 270 top
IC6  15.22,53.66 270 top
IC7  14.27,38.1 90 top
IC8  14.27,34.61 270 top
IC9  15.22,25.4 0 top
IC10  14.27,14.29 90 top
IC11  14.27,11.11 270 top
J1  19.66,42.55 90 bottom
J2  7.6,42.55 90 bottom
J3  19.66,30.48 90 bottom
J4  7.6,30.48 90 bottom
J5  19.66,18.41 90 bottom
J6  7.6,18.41 90 bottom
J7  19.66,6.35 90 bottom
J8  7.6,6.35 90 bottom
JP2  13,102.23 270 top
JP4  41.89,73.66 270 top
LED1  29.19,42.55 90 bottom
LED2  29.19,30.48 90 bottom
LED3  29.19,18.41 90 bottom
LED4  29.19,6.35 90 bottom
OK1  39.03,24.45 270 bottom
Q1  34.91,102.23 180 top
Q2  47.6,102.23 180 top
Q3  5.69,77.47 90 bottom
R1  38.08,104.78 180 top
R2  32.36,101.6 270 top
R3  37.44,101.6 270 top
R4  39.98,101.6 270 top
R5  42.52,101.6 270 top
R6  45.06,101.6 270 top
R7  50.14,101.6 270 top
R8  52.68,101.6 270 top
R9  54.91,101.6 90 top
R10  32.36,79.38 90 top
R11  37.44,79.38 90 top
R12  39.98,79.38 90 top
R13  42.52,79.38 90 top
R14  45.06,79.38 90 top
R15  50.14,79.38 90 top
R16  52.68,79.38 90 top
R17  11.25,72.71 270 top
R18  13.95,60.33 90 top
R19  15.54,60.33 90 top
R20  17.12,60.33 90 top
R21  18.71,60.33 90 top
R22  28.24,60.01 270 top
R23  29.82,60.01 90 top
R24  7.92,58.42 0 top
R25  22.52,57.78 180 top
R26  7.92,56.83 0 top
R27  22.52,56.2 180 top
R28  7.92,51.44 0 top
R29  22.52,51.44 180 top
R30  7.92,49.85 0 top
R31  22.52,49.53 180 top
R32  9.5,42.55 270 top
R33  29.19,38.1 90 top
R34  9.5,30.48 90 top
R35  46.65,26.99 90 bottom
R36  29.19,26.04 90 top
R37  32.05,23.81 90 bottom
R38  9.5,18.41 270 top
R39  34.59,17.14 90 top
R40  36.17,17.14 90 top
R41  29.19,13.97 90 top
R42  29.19,10.79 270 top
R43  9.5,6.35 90 top
SW1  13.31,90.17 0 bottom
SW2  49.83,65.41 0 bottom
SW3  29.51,65.41 0 bottom
SW4  9.19,65.41 0 bottom
U$2  [3,0]  35.54,44.45 0 bottom
U$3  [3,0]  53.32,24.45 0 bottom
U$4  [3,0]  35.54,4.45 0 bottom
U$5  [ROHS]  32.36,59.05 0 top
UC1  18.39,74.3 270 top
X1  45.7,36.51 0 bottom
X2  45.7,12.38 0 bottom

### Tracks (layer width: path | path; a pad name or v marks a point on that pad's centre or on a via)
+3V3  (via drill 0.6)
  Top 0.254: C2.1 35.86,95.47 35.86,94.61 35.54,94.3 IC2.16 | v55.22,90.81 IC3.10 | v42.52,90.81 43.16,91.44 IC2.10 | C9.1 22.68,78.32 | v24.43,79.69 23.95,79.22 23,79.22 22.62,78.84 C9.1 | C9.1 22.64,78.24 UC1.36 | C8.1 14.14,78.4 UC1.1 | v12.68,78.26 12.94,78.53 C8.1 | UC1.48 15.62,78.53 C8.1 | 13,71.91 13,72.55 13.49,73.05 UC1.9 | R17.2 11.31,71.91 13,71.91 | C11.1 13,70.54 13,71.91 | C11.1 | v14.58,70.48 C11.1 | v20.62,67.15 20.62,67.63 21.57,68.58 21.99,68.58 C13.1 22.2,69.85 21.89,70.17 21.27,70.17 UC1.24 | IC4.12 37.1,55.56 36.17,55.56 35.86,55.88 35.86,63.82 33.32,66.36 26.33,66.36 25.7,66.99 25.7,69.85 v26.01,70.17 | R39.2 34.59,25.72 v37.44,28.57
  Top 0.406: 35.54,91.12 IC2.16 | v35.22,91.12 35.54,91.12 | 35.54,91.12 36.81,89.85 38.08,89.85 39.03,90.81 v42.52,90.81 | IC3.16 v47.6,90.81 46.97,90.81 46.02,89.85 C6.1 | 24.11,95.99 IC1.2 23.79,96.31 23.79,97.47 24.74,98.42 28.24,98.42 28.55,98.11 v28.55,95.57 28.55,90.81 | v17.76,85.41 18.71,86.36 v24.43,86.36 v28.24,86.36 28.87,87 28.87,87.84 C5.1 28.77,89.64 28.55,89.85 28.55,90.81 | 45.7,75.88 48.56,75.88 55.86,68.58 55.86,49.21 47.6,40.96 47.6,39.05 37.44,28.89 v37.44,28.57 | 45.7,75.88 v39.03,75.88 | 45.7,75.88 JP4.1 | 28.55,90.81 v32.05,90.81
  Bottom 0.254: v47.6,90.81 48.24,91.44 54.59,91.44 v55.22,90.81 | v24.43,86.36 v24.43,79.69 | v17.76,85.41 17.76,81.44 16.49,80.17 | 16.49,80.17 14.58,78.26 | 14.58,78.26 v12.68,78.26 | 14.58,78.26 v14.58,70.48 | v20.62,67.15 20.62,70.48 20.46,70.64 | 16.49,80.17 16.49,80.01 17.44,79.06 17.44,72.23 18.55,71.12 19.98,71.12 20.46,70.64 | v26.01,70.17 25.54,70.64 20.46,70.64
  Bottom 0.406: v42.52,90.81 v47.6,90.81 | v32.05,90.81 32.36,91.12 v35.22,91.12 | v28.24,86.36 30.46,84.14 30.46,81.28 33.63,78.11 36.81,78.11 v39.03,75.88 | R37.2 C24.1 33.53,28.26 OK1.8 34.58,28.57 v37.44,28.57 | C4.+ 28.55,97.16 v28.55,95.57
+5V
  Top 0.254: IC4.4 31.44,56.2 32.68,56.2 33.32,55.56 33.32,54.61 34.91,53.02 38.08,53.02 39.13,54.08 C18.1 C15.1 39.13,57.89 40.3,59.05 45.06,59.05 46.65,57.47 46.65,55.88 47.29,55.24 IC5.6
+5VD  (via drill 0.6)
  Top 0.406: IC10.5 13.63,13.34 13.64,13.34 14.27,13.34 | C27.1 11.51,14.29 14.27,14.29 | 14.27,14.29 14.27,19.68 16.07,21.49 C26.1 16.07,24.2 IC9.2 16.17,25.4 19.35,28.57 19.35,32.38 v18.39,33.34 | 14.27,14.29 14.27,13.34 | 14.27,13.34 14.27,12.7 14.9,12.06 IC11.5 | 14.27,37.15 14.27,38.1 11.51,38.1 C23.1 | IC7.5 14.26,37.15 14.27,37.15 | 14.27,37.15 14.27,36.2 | 14.27,36.2 14.9,35.56 IC8.5 | 14.27,36.2 v14.27,34.61
  Bottom 0.406: v18.39,33.34 17.12,34.61 v14.27,34.61
AOUT
  Top 0.254: R32.1 9.61,43.5 10.77,43.5 11.73,42.55 J2.TIP
CH_A
  Top 0.254: 31.36,58.1 IC4.1 30.55,58.17 30.46,58.26 27.13,58.26 26.33,59.05 26.33,59.37 24.74,60.96 23.16,60.96 20.62,63.5 16.17,63.5 13.95,61.28 R18.2
CH_B
  Top 0.254: IC4.2 31.39,57.47 30.46,57.47 30.14,57.78 26.65,57.78 25.7,58.74 25.7,59.05 24.43,60.33 22.84,60.33 20.3,62.87 16.49,62.87 15.54,61.91 R19.2
CH_C
  Top 0.254: IC4.7 31.39,54.29 27.92,54.29 25.06,57.15 25.06,58.74 24.11,59.69 22.52,59.69 19.98,62.23 17.44,62.23 17.12,61.91 R20.2
CH_D
  Top 0.254: R21.2 18.81,61.28 19.98,61.28 22.2,59.05 23.79,59.05 24.43,58.42 24.43,56.83 27.67,53.59 IC4.8
DAC_MOSI
  Top 0.254: IC4.11 37.1,54.93 35.86,54.93 35.22,55.56 35.22,63.5 33,65.72 26.01,65.72 25.06,66.67 25.06,71.44 23.45,73.05 UC1.28
DAC_SCK
  Top 0.254: IC4.10 37.08,54.29 35.54,54.29 34.59,55.24 34.59,63.18 32.68,65.09 25.7,65.09 24.43,66.36 24.43,71.12 23.5,72.05 UC1.26
DAC_SS
  Top 0.254: IC4.9 37.05,53.66 35.22,53.66 33.95,54.93 33.95,62.87 32.36,64.45 25.38,64.45 23.79,66.04 23.79,69.85 22.64,71 UC1.25
DISP_CHAR0
  Top 0.254: R9.1 54.91,97.16 57.45,94.61 57.45,83.98 54.59,81.12 54.59,78.74 53.32,77.47 30.46,77.47 29.03,78.9 29.03,80.96 26.65,83.34 21.25,83.34 18.64,80.74 UC1.42
DISP_CHAR1
  Top 0.254: R1.1 49.51,104.78 49.83,105.09 52.05,105.09 53,104.14 55.22,104.14 55.86,103.5 55.86,97.16 58.08,94.93 58.08,83.82 55.07,80.8 55.07,78.42 53.64,76.99 30.14,76.99 28.55,78.58 28.55,80.64 26.33,82.87 21.57,82.87 19.14,80.44 UC1.41
DISP_EN  (via drill 0.6)
  Top 0.254: v40.62,96.2 IC2.12 | v52.68,96.2 IC3.12 | v33.95,86.04 32.84,86.04 31.09,84.3 20.62,84.3 17.14,80.82 UC1.45
  Bottom 0.254: v52.68,96.2 51.41,96.2 50.94,96.68 49.19,96.68 48.72,96.2 46.65,96.2 46.18,95.73 42.84,95.73 42.37,96.2 v40.62,96.2 39.35,94.93 39.35,91.44 v33.95,86.04
DISP_SCK  (via drill 0.6)
  Top 0.254: v33.32,84.77 32.36,84.77 31.41,83.82 20.93,83.82 18.14,81.03 UC1.43 | v53.95,95.25 IC3.11 | v41.89,95.25 IC2.11
  Bottom 0.254: v53.95,95.25 52.21,95.25 51.73,95.73 51.1,95.73 50.62,96.2 49.51,96.2 49.03,95.73 46.97,95.73 46.49,95.25 v41.89,95.25 40.62,95.25 39.98,94.61 39.98,91.12 35.22,86.36 35.22,85.41 34.59,84.77 v33.32,84.77
DISP_SER  (via drill 0.6)
  Top 0.254: IC2.14 38.08,92.08 v37.13,91.12 | v33,87 30.78,84.77 20.3,84.77 16.64,81.12 UC1.46
  Bottom 0.254: v33,87 33.95,87 37.13,90.17 v37.13,91.12
ENC_A
  Top 0.254: SW1.B 10.77,82.63 10.77,77.79 12.02,76.55 UC1.2
ENC_B
  Top 0.254: SW1.A 15.85,82.71 15.85,83.5 15.22,84.14 10.14,84.14 9.5,83.5 9.5,81.6 10.14,80.96 10.14,77.47 11.56,76.05 UC1.3
ENC_CLICK
  Top 0.254: 14.12,75.56 UC1.4 11.11,75.55 9.5,77.15 9.5,80.64 8.87,81.28 8.87,86.36 11.09,88.58 11.09,96.89 SW1.E
GATE_A
  Top 0.254: UC1.21 19.64,69.04 15.54,64.93 3.95,64.93 2.04,63.02 2.04,48.74 6.33,44.45 6.33,40.01 5.38,39.05 5.38,33.97 6.33,33.02 6.33,29.21 7.6,27.94 17.12,27.94 18.39,29.21 18.39,32.07 17.44,33.02 17.44,36.83 16.17,38.1 IC7.2
GATE_B
  Top 0.254: UC1.22 20.14,68.74 15.85,64.45 4.27,64.45 2.52,62.71 2.52,49.21 6.96,44.77 6.96,41.59 9.82,38.73 9.82,36.2 11.41,34.61 IC8.2
GATE_C
  Top 0.254: UC1.18 18.14,69.28 14.74,65.88 3.31,65.88 1.09,63.66 1.09,12.7 5.69,8.1 5.69,5.08 7.28,3.49 16.81,3.49 18.39,5.08 18.39,8.57 17.44,9.53 17.44,13.02 16.17,14.29 IC10.2
GATE_D
  Top 0.254: UC1.19 18.64,68.83 15.22,65.41 3.63,65.41 1.57,63.34 1.57,48.26 5.69,44.13 5.69,40.32 4.74,39.37 4.74,33.66 5.69,32.7 5.69,26.99 5.38,26.67 5.38,24.77 5.69,24.45 5.69,14.92 5.38,14.61 5.38,13.02 5.69,12.7 5.69,10.79 6.96,9.53 8.55,9.53 10.14,11.11 IC11.2
GND  (via drill 0.6)
  Top 0.254: 19.35,71.44 19.14,71.23 UC1.20
  other vias: 5.69,52.07 23.47,54.61 38.4,95.89 50.14,89.53 43.79,103.82 33.95,105.09 56.18,84.77 7.92,80.01 27.6,56.52 1.57,91.76 15.22,88.9 20.3,65.72 19.03,72.07 12.68,22.86 40.94,53.98 15.7,73.03 57.13,99.06 11.41,1.91 23.47,1.91 4.42,12.7 4.42,22.86 23.47,105.09 20.78,76.83 25.38,76.99 9.66,70.48 16.01,76.83 28.87,82.87 38.71,59.05 57.13,78.74 57.13,68.58 57.13,58.42 57.13,48.26 57.13,38.1 57.13,17.78 57.13,7.62 52.68,1.91 42.52,1.91 1.88,7.62 32.05,20.64 27.28,90.49 36.81,62.23 33.63,99.38 48.24,45.72 49.51,69.85 4.42,67.31 15.22,57.78 15.22,54.61 20.3,59.37 3.79,50.8 3.79,56.52 29.19,49.53 25.38,87.95 23.79,87.95 22.2,87.95 20.93,93.66 22.52,93.66 20.93,92.08 22.52,92.08 24.11,92.08 25.7,93.66 24.11,93.66 25.7,92.08 27.28,92.08 27.28,93.66
  pour Top: -0.02,106.68 -0.02,0 25.38,0 25.7,49.53 27.6,51.44 48.88,51.44 50.14,52.7 50.14,58.42 48.88,59.69 36.49,59.69 36.49,60.64 49.19,60.64 51.1,58.74 51.1,52.39 49.19,50.48 27.92,50.48 26.65,49.21 26.65,0 59.03,0 59.03,106.68
  pour Bottom: -0.02,106.68 -0.02,0 25.38,0 25.7,49.53 27.6,51.44 48.88,51.44 50.14,52.7 50.14,58.42 48.88,59.69 36.49,59.69 36.49,60.64 49.19,60.64 51.1,58.74 51.1,52.39 49.19,50.48 27.92,50.48 26.65,49.21 26.65,0 59.03,0 59.03,106.68
JTCK
  Top 0.254: JP4.4 44.43,72.39 42.84,70.8 41.25,70.8 40.62,71.44 39.19,71.44 35.54,75.09 28.87,75.09 26.65,77.31 26.65,79.38 25.38,80.64 23.79,80.64 23,79.85 21.41,79.85 21.14,79.58 UC1.37
JTDI  (via drill 0.6)
  Top 0.254: v41.89,71.75 41.57,72.07 39.35,72.07 35.86,75.56 29.19,75.56 27.13,77.63 27.13,79.69 25.54,81.28 23.63,81.28 22.68,80.33 21.09,80.33 20.64,79.88 | UC1.38 20.64,79.88 | 20.64,79.88
  Bottom 0.254: v41.89,71.75 JP4.8
JTDO
  Top 0.254: JP4.6 43.16,73.03 42.84,72.71 39.51,72.71 36.17,76.04 29.51,76.04 27.6,77.95 27.6,80.01 25.7,81.92 23.47,81.92 22.36,80.8 20.78,80.8 20.14,80.17 UC1.39
JTMS
  Top 0.254: JP4.2 45.7,72.71 43.16,70.17 40.94,70.17 40.3,70.8 39.03,70.8 35.22,74.61 28.55,74.61 27.12,76.05 UC1.34
LED_1
  Top 0.254: 29.09,37.15 R33.1 29.4,37.47 35.54,37.47 45.7,47.62 53,47.62 54.59,49.21 54.59,63.82 53.48,64.93 49.83,64.93 48.88,65.88 40.3,65.88 | UC1.33 22.66,75.56 26.81,75.56 30.62,71.75 34.43,71.75 40.3,65.88 | 40.3,65.88
LED_2
  Top 0.254: UC1.32 26.53,75.05 30.3,71.28 34.11,71.28 39.98,65.41 48.56,65.41 49.51,64.45 53,64.45 53.95,63.5 53.95,49.53 52.68,48.26 45.38,48.26 35.22,38.1 33,38.1 30.46,40.64 30.46,41.91 29.82,42.55 28.55,42.55 27.92,41.91 27.92,25.72 28.45,25.18 R36.1
LED_3
  Top 0.254: R41.1 28.97,13.34 28.24,13.34 27.28,14.29 27.28,44.13 32.36,49.21 49.83,49.21 52.05,51.44 52.05,59.37 49.83,61.59 41.41,61.59 33.16,69.85 29.35,69.85 25.65,73.55 UC1.29
LED_4  (via drill 0.6)
  Top 0.254: R42.1 28.97,11.43 28.55,11.43 26.65,13.34 26.65,44.45 32.05,49.85 49.51,49.85 51.41,51.75 51.41,59.05 49.51,60.96 41.25,60.96 32.84,69.37 29.03,69.37 26.01,72.39 v25.38,72.39 | v20.62,72.71 20.78,72.55 UC1.27
  Bottom 0.254: v25.38,72.39 24.74,73.03 20.93,73.03 v20.62,72.71
MIDI_RX  (via drill 0.6)
  Top 0.254: 49.35,63.82 48.24,64.93 39.67,64.93 33.79,70.8 29.98,70.8 26.24,74.55 UC1.31 | 49.35,63.82 | 49.35,63.82 53.32,59.85 53.32,50.48 v53,50.16 | v55.22,45.09 53.64,45.09 53,44.45 53,41.59 49.83,38.42 47.92,38.42 39.98,30.48 39.98,25.08 v38.08,23.18
  Bottom 0.254: v55.22,45.09 54.59,45.72 54.59,47.62 53,49.21 v53,50.16 | R37.1 32.26,23.18 OK1.6 v38.08,23.18
MIDI_TX  (via drill 0.6)
  Top 0.254: UC1.30 25.95,74.05 29.67,70.33 33.48,70.33 39.35,64.45 47.92,64.45 52.68,59.69 52.68,51.12 51.73,50.16 v51.73,49.53 | R40.2 36.17,19.05 40.62,23.5 40.62,30.16 48.24,37.78 50.14,37.78 53.95,41.59 v53.95,44.13
  Bottom 0.254: v51.73,49.53 53.95,47.31 v53.95,44.13
N$1
  Top 0.254: DISP1.16 Q2.C
N$2
  Top 0.254: R29.2 21.57,51.33 C22.1 20.08,51.12 IC6.9 17.12,51.12 16.17,52.07 16.17,58.42 17.12,59.37 R20.1
N$3
  Top 0.254: DISP1.11 Q1.C
N$4  (via drill 0.6)
  Top 0.254: UC1.5 10.34,75.05 8.87,76.52 8.02,76.52 C7.2 7.81,76.52 7.28,76.52 5.69,78.11 v5.69,78.42
  Bottom 0.254: v5.69,78.42 Q3.2
N$5  (via drill 0.6)
  Top 0.254: UC1.6 8.2,74.55 C10.2 7.7,74.61 7.28,74.61 v5.69,76.2
  Bottom 0.254: Q3.1 v5.69,76.2
N$6
  Top 0.254: Q2.B 48.72,103.5 49.19,103.5 50.14,104.46 51.73,104.46 52.68,103.5 54.59,103.5 54.91,103.19 R9.2
N$7
  Top 0.254: Q1.B 35.86,104.46 36.17,104.78 R1.2
N$8
  Bottom 0.254: D3.C R35.1 45.48,26.14 45.06,25.72 OK1.2
N$9
  Bottom 0.254: X1.4 49.51,40.32 49.51,28.89 48.45,27.84 R35.2
N$10
  Top 0.254: R40.1 36.2,16.27 X2.5
N$11
  Top 0.254: DISP1.17 R7.2
N$12
  Bottom 0.254: D3.A 46.65,21.91 45.38,23.18 OK1.3 42.84,23.18 41.89,24.13 41.89,40.32 X1.5
N$13
  Top 0.254: R39.1 34.59,15.56 35.86,14.29 48.88,14.29 49.59,15 X2.4
N$14
  Top 0.254: IC7.4 11.41,39.05 9.5,40.96 R32.2
N$15
  Top 0.254: DISP1.12 R3.2
N$16
  Top 0.254: DISP1.10 R2.2
N$17
  Top 0.254: R10.2 DISP1.9
N$18
  Top 0.254: R11.2 DISP1.7
N$19
  Top 0.254: R16.2 DISP1.1
N$20
  Top 0.254: DISP1.18 R8.2
N$22
  Top 0.254: DISP1.15 R6.2
N$23
  Top 0.254: DISP1.14 R5.2
N$24
  Top 0.254: R12.2 DISP1.6
N$25
  Top 0.254: R13.2 DISP1.5
N$26
  Top 0.254: R14.2 DISP1.4
N$27
  Top 0.254: R15.2 DISP1.2
N$28
  Top 0.254: DISP1.13 R4.2
N$29
  Top 0.254: R34.2 9.5,32.07 10.14,32.7 13.95,32.7 14.9,33.66 IC8.4
N$30
  Top 0.254: R6.1 45.28,102.23 45.7,102.23 46.33,101.6 46.33,97.16 46.65,96.84 46.65,91.76 43.16,88.27 IC2.7
N$31  (via drill 0.6)
  Top 0.254: v50.14,95.25 IC3.14 | v45.7,93.66 45.28,93.24 IC2.9
  Bottom 0.254: v50.14,95.25 47.29,95.25 v45.7,93.66
N$32
  Top 0.254: R3.1 37.23,102.23 36.49,102.23 36.17,101.92 36.17,96.84 36.81,96.2 IC2.15
N$33
  Top 0.254: R2.1 32.26,102.55 31.41,102.55 31.09,102.23 31.09,97.16 32.68,95.57 32.68,93.98 33.63,93.03 33.63,90.49 35.54,88.58 IC2.1
N$34
  Top 0.254: R10.1 32.58,78.74 33.32,78.74 33.63,79.06 33.63,82.87 36.81,86.04 IC2.2
N$35
  Top 0.254: R11.1 37.23,78.74 36.81,78.74 36.17,79.38 36.17,84.45 36.81,85.09 37.44,85.09 38.08,85.72 IC2.3
N$36  (via drill 0.6)
  Top 0.254: v41.25,84.77 39.98,84.77 39.35,85.41 IC2.4 | v53.95,84.77 53.95,79.06 53.42,78.53 R16.1
  Bottom 0.254: v41.25,84.77 v53.95,84.77
N$37  (via drill 0.6)
  Top 0.203: 55.86,91.76 55.86,94.61
  Top 0.254: R8.1 52.79,102.55 53.32,102.55 53.95,101.92 53.95,97.16 55.86,95.25 55.86,94.61 | 55.86,91.76 56.18,91.44 v56.18,89.53 | IC2.5 40.62,88.58 v40.94,88.9
  Bottom 0.254: v56.18,89.53 55.86,89.85 54.91,89.85 53.95,90.81 48.88,90.81 47.92,89.85 41.89,89.85 v40.94,88.9
N$38  (via drill 0.6)
  Top 0.203: 43.79,91.76 43.79,94.93
  Top 0.254: v51.41,103.19 50.46,103.19 50.14,102.87 R7.1 | IC2.6 41.89,88.27 43.79,90.17 43.79,91.76 | 43.79,94.93 v43.79,101.6
  Bottom 0.254: v43.79,101.6 44.11,101.28 49.51,101.28 v51.41,103.19
N$39  (via drill 0.6)
  Top 0.254: R5.1 42.42,102.55 41.89,102.55 41.25,101.92 v41.25,99.69 | IC3.15 v48.88,99.69
  Bottom 0.254: v48.88,99.69 48.56,100.01 41.57,100.01 v41.25,99.69
N$40
  Top 0.254: R12.1 40.2,78.74 40.62,78.74 41.25,79.38 41.25,82.87 42.84,84.45 46.97,84.45 47.6,85.09 IC3.1
N$41
  Top 0.254: R13.1 42.74,78.74 43.16,78.74 43.79,79.38 43.79,83.19 44.43,83.82 47.29,83.82 48.88,85.41 IC3.2
N$42
  Top 0.254: R14.1 45.28,78.74 46.33,78.74 48.88,81.28 48.88,84.14 50.14,85.41 IC3.3
N$43
  Top 0.254: R15.1 50.36,78.74 50.78,78.74 51.41,79.38 IC3.4
N$44  (via drill 0.6)
  Top 0.203: 52.05,91.44 52.05,94.61
  Top 0.254: IC3.5 52.68,88.9 52.05,89.53 52.05,91.44 | 52.05,94.61 50.78,95.89 50.78,96.84 51.41,97.47 v51.41,99.69 | v38.71,101.6 38.71,101.92 39.25,102.45 R4.1
  Bottom 0.254: v51.41,99.69 50.46,100.65 39.67,100.65 v38.71,101.6
N$45
  Top 0.254: R38.2 9.5,16.51 10.78,15.24 IC10.4
N$46
  Top 0.254: R43.2 9.5,8.26 10.14,8.89 13.63,8.89 14.9,10.16 IC11.4
N$47
  Top 0.254: R24.2 8.82,58.48 C14.2 10.2,58.42 11.41,58.42 12.15,57.68 IC6.1
N$48
  Top 0.254: R38.1 9.61,19.37 10.46,19.37 11.41,18.41 J6.TIP
N$49
  Top 0.254: R43.1 9.72,5.71 10.46,5.71 11.09,6.35 J8.TIP
N$50
  Top 0.254: IC6.7 10.35,49.85 C21.2 8.98,49.63 R30.2
N$51
  Top 0.254: IC6.8 20.08,49.85 C22.2 21.57,49.63 R31.2
N$52
  Top 0.254: IC6.14 19.93,57.47 C16.2 21.62,57.84 R25.2
N$53
  Top 0.254: R24.1 R26.1 6.01,56.83 4.74,55.56 4.74,47.94 7.6,45.09 16.49,45.09 21.89,39.69 21.89,28.26 23.16,26.99 23.16,16.83 24.46,15.52 J7.TIP
N$54
  Top 0.254: R33.2 LED1.A
N$55
  Top 0.254: J3.TIP 24.46,39.65 22.84,41.27 22.84,43.81 23.37,44.35 R31.1 R29.1
N$56
  Top 0.406: JP2.2 JP2.1 18.71,104.14 D1.A
N$57
  Top 0.254: R34.1 9.61,29.53 10.46,29.53 11.41,30.48 J4.TIP
N$58
  Top 0.254: R25.1 R27.1 24.11,56.2 25.7,54.61 25.7,53.34 25.06,52.7 25.06,48.26 24.46,47.66 J1.TIP
N$59
  Top 0.254: R27.2 21.62,56.14 C16.1 20.24,56.2 IC6.13 17.12,56.2 16.81,56.52 16.81,58.1 17.12,58.42 18.39,58.42 18.71,58.74 R21.1 18.71,59.37
N$60
  Top 0.254: R19.1 15.54,59.37 14.27,58.1 14.27,52.07 13.31,51.12 IC6.6 10.35,51.12 C21.1 8.87,51.33 R28.2
N$61
  Top 0.254: 8.65,56.83 R26.2 8.82,56.78 C14.1 10.51,56.78 11.09,56.2 IC6.2 13.31,56.2 13.63,56.52 13.63,58.42 13.95,58.74 R18.1
N$63
  Top 0.254: J5.TIP 24.46,26.63 22.52,28.57 22.52,40.01 16.17,46.35 11.41,46.35 8.87,48.9 7.28,48.9 7.07,49.11 R30.1 R28.1
N$64
  Top 0.406: JP2.10 JP2.9 7.29,104.14 D2.C
N$65
  Top 0.254: LED2.A R36.2
N$66
  Top 0.254: LED3.A R41.2
N$67
  Top 0.254: R42.2 28.97,10.16 28.55,10.16 27.92,9.53 27.92,6.35 LED4.A
RESET  (via drill 0.6)
  Top 0.254: JP4.10 39.35,73.66 36.49,76.52 29.82,76.52 28.08,78.26 28.08,80.33 26.01,82.39 22.52,82.39 v21.89,81.76 | v19.03,76.83 16.24,74.05 UC1.7 12.75,74.05 12.2,73.5 11.31,73.5 R17.1
  Bottom 0.254: v21.89,81.76 19.03,78.9 v19.03,76.83
SWITCH_0  (via drill 0.6)
  Top 0.254: SW2.A1 SW2.A2 47.29,67.94 40.3,67.94 35.06,73.18 v31.25,73.18 | v20.62,75.25 19.35,75.25 16.64,72.55 UC1.15
  Bottom 0.254: v31.25,73.18 30.14,74.3 21.89,74.3 21.57,74.61 21.25,74.61 v20.62,75.25
SWITCH_1  (via drill 0.6)
  Top 0.254: SW3.A2 SW3.A1 | v19.66,73.82 18.71,73.82 17.14,72.25 UC1.16
  Bottom 0.254: SW3.A2 26.97,67.94 28.55,69.53 28.55,72.55 27.44,73.66 21.57,73.66 21.41,73.82 v19.66,73.82
SWITCH_2
  Top 0.254: SW4.A2 SW4.A1 11.73,67.94 14.9,67.94 16.14,69.19 UC1.14
VCC  (via drill 0.6)
  Top 0.406: IC9.3 12.61,26.5 C25.1 10.88,26.25 v10.77,26.35 | C19.1 9.5,53.02 v10.14,53.66 IC6.4 | v26.65,52.07 26.97,52.39 44.75,52.39 45.38,53.02 45.38,55.88 44.75,56.52 IC5.2 | v21.89,45.4 19.03,45.4 14.9,49.53 v14.9,50.16 | 21.57,99.06 6.96,99.06 4.74,96.84 v4.74,87 4.74,84.77 1.57,81.6 v1.57,66.67 | IC1.3 21.57,96.25 21.57,99.06 | D1.C 26.97,100.33 27.6,100.97 v28.55,100.97 27.28,99.69 23.47,99.69 22.84,99.06 21.57,99.06
  Bottom 0.406: 7.92,53.66 v10.14,53.66 | 7.92,53.66 1.57,53.66 | 1.57,53.66 1.57,37.78 10.77,28.57 v10.77,26.35 | 1.57,53.66 v1.57,66.67 | v14.9,50.16 9.5,50.16 7.92,51.75 7.92,53.66 | v26.65,52.07 24.11,49.53 24.11,47.62 v21.89,45.4 | v28.55,100.97 27.11,102.41 C1.+ | C12.+ 4.74,89.82 v4.74,87
VEE  (via drill 0.6)
  Top 0.406: v4.11,60.33 v11.09,60.33 | C20.2 20.93,53.02 v20.3,53.66 IC6.11 | v3.15,85.72 3.15,96.52 3.47,96.84 D2.A 3.47,98.42 v2.2,97.16
  Bottom 0.406: v3.15,85.72 3.15,61.28 v4.11,60.33 | v11.09,60.33 17.76,53.66 v20.3,53.66 | C3.- 2.52,94.01 2.2,94.33 v2.2,97.16
VREF
  Top 0.254: R23.2 29.93,60.96 31.41,60.96 32.68,59.69 32.68,57.15 32.38,56.84 IC4.3 29.23,56.84 C17.1
VREF/2  (via drill 0.6)
  Top 0.254: IC6.10 17.12,52.39 16.81,52.7 16.81,54.61 17.12,54.93 IC6.12 21.57,54.93 v21.89,54.61 | IC6.5 13.31,52.39 13.63,52.7 13.63,54.61 13.31,54.93 IC6.3 9.5,54.93 v9.19,55.24 | v22.52,63.18 22.52,62.55 23.47,61.59 25.06,61.59 27.5,59.16 R22.2 R23.1
  Bottom 0.254: v9.19,55.24 13,55.24 16.81,51.44 21.25,51.44 21.89,52.07 v21.89,54.61 21.89,61.91 21.89,62.55 v22.52,63.18

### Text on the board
tPlace: Red stripe | cc-by-sa Émilie Gillet, 2013. v0.3 | Yarns
bPlace: Yarns | cc-by-sa Émilie Gillet, 2013. v0.3
tNames: -12V | GND | +12V | mini JTAG
bValues: TAP | START/STOP | REC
